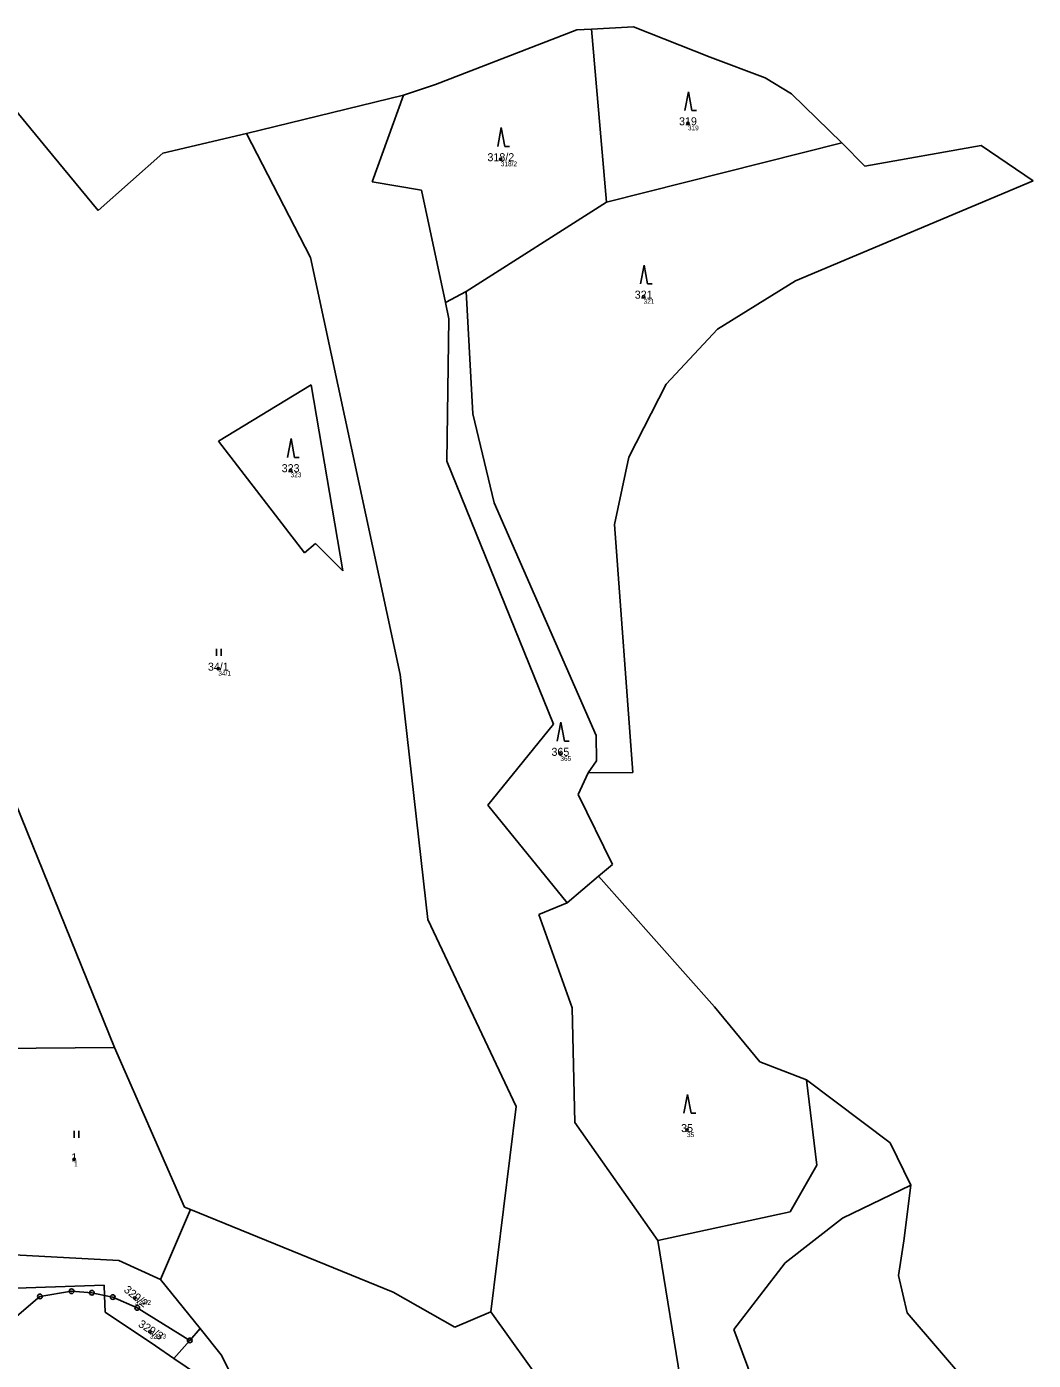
# Model space of a CAD drawing. Extents: x -868010 to -864567, y -1041968 to -1040406.
# Drawn here: x -865068.7 to -864854.9, y -1040959.8 to -1040676.6 of the extents above; entities that cross this region are included whole.
import ezdxf

# ---------------------------------------------------------------- set-up
doc = ezdxf.new("R2010")
doc.units = 0
for name, color, linetype in [('Definiční body', 7, 'Continuous'), ('Hranice parcel', 7, 'Continuous'), ('Parcelní čísla', 7, 'Continuous'), ('Značky bodu BP', 7, 'Continuous'), ('Značky kultur', 7, 'Continuous')]:
    doc.layers.add(name, color=color, linetype=linetype)

msp = doc.modelspace()

# ---------------------------------------------------------------- linework, layer by layer
at = {"layer": 'Definiční body'}
for centre in [(-864928.24, -1040697.07994), (-864967.98, -1040704.70994), (-864937.65, -1040733.90994), (-865012.62, -1040770.75994), (-865027.97, -1040812.91994), (-864955.33, -1040831.00994), (-864928.43, -1040910.92994), (-865058.58, -1040917.14994), (-865045.7, -1040946.55994), (-865042.51, -1040953.70994)]:
    msp.add_circle(centre, 0.25, dxfattribs=at)
at = {"layer": 'Hranice parcel'}
for p, q in [((-864945.5, -1040713.85), (-864948.71, -1040677.1)), ((-865077.15, -1040686.93), (-865063.19, -1040703.84)), ((-864988.64, -1040691.1), (-865021.96, -1040699.26)), ((-864988.64, -1040691.1), (-864995.32, -1040709.49)), ((-864988.64, -1040691.1), (-864981.88, -1040688.87)), ((-865021.96, -1040699.26), (-865039.73, -1040703.45)), ((-865021.96, -1040699.26), (-865008.4, -1040725.6)), ((-864945.5, -1040713.85), (-864895.58, -1040701.25)), ((-864895.58, -1040701.25), (-864890.64, -1040706.19)), ((-864890.64, -1040706.19), (-864865.98, -1040701.8)), ((-864865.98, -1040701.8), (-864854.89, -1040709.33)), ((-865063.19, -1040703.84), (-865053.49, -1040715.59)), ((-865039.73, -1040703.45), (-865053.49, -1040715.59)), ((-864995.32, -1040709.49), (-864984.8, -1040711.27)), ((-864984.8, -1040711.27), (-864979.73, -1040735.14)), ((-864905.4, -1040730.54), (-864854.89, -1040709.33)), ((-864975.3, -1040732.8), (-864945.5, -1040713.85)), ((-865008.4, -1040725.6), (-864989.33, -1040814.16)), ((-864979.73, -1040735.14), (-864975.3, -1040732.8)), ((-864975.3, -1040732.8), (-864973.89, -1040758.79)), ((-864978.98, -1040738.62), (-864979.73, -1040735.14)), ((-864979.45, -1040768.85), (-864978.98, -1040738.62)), ((-865027.93, -1040764.58), (-865008.26, -1040752.62)), ((-865008.26, -1040752.62), (-865001.5, -1040792.14)), ((-864973.89, -1040758.79), (-864969.37, -1040777.68)), ((-865009.66, -1040788.34), (-865027.93, -1040764.58)), ((-864979.45, -1040768.85), (-864956.82, -1040824.71)), ((-864969.37, -1040777.68), (-864947.74, -1040827.13)), ((-865007.36, -1040786.32), (-865009.66, -1040788.34)), ((-865001.5, -1040792.14), (-865007.36, -1040786.32)), ((-864989.33, -1040814.16), (-864983.44, -1040866.22)), ((-864970.76, -1040841.94), (-864956.82, -1040824.71)), ((-864947.74, -1040827.13), (-864947.63, -1040832.5)), ((-864947.63, -1040832.5), (-864949.44, -1040835.03)), ((-864951.53, -1040839.63), (-864949.44, -1040835.03)), ((-865050, -1040893.36), (-865070.98, -1040841.62)), ((-864944.28, -1040854.49), (-864951.53, -1040839.63)), ((-864953.86, -1040862.63), (-864970.76, -1040841.94)), ((-864947.26, -1040856.97), (-864944.28, -1040854.49)), ((-864953.86, -1040862.63), (-864947.26, -1040856.97)), ((-864922.63, -1040884.77), (-864947.26, -1040856.97)), ((-864959.93, -1040865.15), (-864953.86, -1040862.63)), ((-864983.44, -1040866.22), (-864964.68, -1040905.94)), ((-864952.82, -1040884.99), (-864959.93, -1040865.15)), ((-864952.23, -1040909.28), (-864952.82, -1040884.99)), ((-864912.96, -1040896.41), (-864922.63, -1040884.77)), ((-865050, -1040893.36), (-865089.72, -1040893.69)), ((-865035.13, -1040927.32), (-865050, -1040893.36)), ((-864903.03, -1040900.28), (-864912.96, -1040896.41)), ((-864903.03, -1040900.28), (-864900.89, -1040918.36)), ((-864885.3, -1040913.62), (-864903.03, -1040900.28)), ((-864964.68, -1040905.94), (-864970.13, -1040949.51)), ((-864934.65, -1040934.35), (-864952.23, -1040909.28)), ((-864880.89, -1040922.66), (-864885.3, -1040913.62)), ((-864906.52, -1040928.28), (-864900.89, -1040918.36)), ((-864880.89, -1040922.66), (-864895.42, -1040929.61)), ((-864882.38, -1040934.48), (-864880.89, -1040922.66)), ((-865033.9, -1040927.77), (-865040.24, -1040942.68)), ((-865033.9, -1040927.77), (-865035.13, -1040927.32)), ((-864990.86, -1040945.37), (-865033.9, -1040927.77)), ((-864934.65, -1040934.35), (-864906.52, -1040928.28)), ((-864895.42, -1040929.61), (-864907.56, -1040939.09)), ((-864928.73, -1040970.79), (-864934.65, -1040934.35)), ((-864883.55, -1040941.82), (-864882.38, -1040934.48)), ((-865073.93, -1040937.25), (-865049.11, -1040938.65)), ((-865049.11, -1040938.65), (-865040.24, -1040942.68)), ((-864907.56, -1040939.09), (-864918.51, -1040953.31)), ((-865031.84, -1040953.09), (-865040.24, -1040942.68)), ((-864881.68, -1040949.76), (-864883.55, -1040941.82)), ((-865052.21, -1040943.87), (-865080.29, -1040944.86)), ((-865052.14, -1040946.04), (-865052.21, -1040943.87)), ((-865052.03, -1040949.57), (-865052.14, -1040946.04)), ((-864977.77, -1040952.79), (-864990.86, -1040945.37)), ((-865041.34, -1040956.77), (-865052.03, -1040949.57)), ((-864970.13, -1040949.51), (-864977.77, -1040952.79)), ((-864970.13, -1040949.51), (-864948.86, -1040979.05)), ((-864866.15, -1040967.76), (-864881.68, -1040949.76)), ((-865031.84, -1040953.09), (-865034.04, -1040955.61)), ((-865027.34, -1040958.67), (-865031.84, -1040953.09)), ((-864918.51, -1040953.31), (-864913.04, -1040967.97)), ((-865037.38, -1040959.44), (-865041.34, -1040956.77)), ((-865034.04, -1040955.61), (-865037.38, -1040959.44)), ((-865029.54, -1040964.73), (-865037.38, -1040959.44)), ((-865027.34, -1040958.67), (-865013.57, -1040985.88))]:
    msp.add_line(p, q, dxfattribs=at)
for points in [[(-864948.71, -1040677.1), (-864951.85, -1040677.21), (-864981.88, -1040688.87)], [(-864948.71, -1040677.1), (-864939.77, -1040676.56), (-864923.5, -1040683.04), (-864911.85, -1040687.41), (-864906.26, -1040690.81), (-864895.58, -1040701.25)], [(-864905.4, -1040730.54), (-864921.99, -1040740.82), (-864932.87, -1040752.51), (-864940.81, -1040767.99), (-864943.81, -1040782.28)], [(-864943.81, -1040782.28), (-864939.96, -1040834.96), (-864949.44, -1040835.03)], [(-865087.04, -1040964.3), (-865065.86, -1040946.27), (-865059.13, -1040945.17), (-865054.8, -1040945.48), (-865052.14, -1040946.04)], [(-865052.14, -1040946.04), (-865050.38, -1040946.41), (-865045.18, -1040948.68), (-865034.04, -1040955.61)]]:
    msp.add_lwpolyline(points, dxfattribs=at)
at = {"layer": 'Značky bodu BP'}
for centre, radius in [((-865065.86, -1040946.26988), 0.5), ((-865065.86, -1040946.26988), 0.0303), ((-865059.13, -1040945.16988), 0.5), ((-865059.13, -1040945.16988), 0.0303), ((-865054.8, -1040945.47988), 0.5), ((-865054.8, -1040945.47988), 0.0303), ((-865050.38, -1040946.40988), 0.5), ((-865050.38, -1040946.40988), 0.0303), ((-865045.18, -1040948.67988), 0.5), ((-865045.18, -1040948.67988), 0.0303), ((-865034.04, -1040955.60988), 0.5), ((-865034.04, -1040955.60988), 0.0303)]:
    msp.add_circle(centre, radius, dxfattribs=at)
at = {"layer": 'Značky kultur'}
for p, q in [((-864928.14, -1040690.38), (-864928.89, -1040694.38)), ((-864927.39, -1040694.38), (-864928.14, -1040690.38)), ((-864927.39, -1040694.38), (-864926.394, -1040694.38)), ((-864967.88, -1040698.01), (-864968.63, -1040702.01)), ((-864967.13, -1040702.01), (-864967.88, -1040698.01)), ((-864967.13, -1040702.01), (-864966.134, -1040702.01)), ((-864937.55, -1040727.21), (-864938.3, -1040731.21)), ((-864936.8, -1040731.21), (-864937.55, -1040727.21)), ((-864936.8, -1040731.21), (-864935.804, -1040731.21)), ((-865012.52, -1040764.06), (-865013.27, -1040768.06)), ((-865011.77, -1040768.06), (-865012.52, -1040764.06)), ((-865011.77, -1040768.06), (-865010.774, -1040768.06)), ((-865028.381, -1040810.22), (-865028.381, -1040808.72)), ((-865027.38, -1040810.22), (-865027.38, -1040808.72)), ((-864955.23, -1040824.31), (-864955.98, -1040828.31)), ((-864954.48, -1040828.31), (-864955.23, -1040824.31)), ((-864954.48, -1040828.31), (-864953.484, -1040828.31)), ((-864928.33, -1040903.35), (-864929.08, -1040907.35)), ((-864927.58, -1040907.35), (-864928.33, -1040903.35)), ((-864927.58, -1040907.35), (-864926.584, -1040907.35)), ((-865058.591, -1040912.58), (-865058.591, -1040911.08)), ((-865057.59, -1040912.58), (-865057.59, -1040911.08))]:
    msp.add_line(p, q, dxfattribs=at)

# ---------------------------------------------------------------- texts
at = {"layer": 'Definiční body'}
for s, height, p in [('319', 0.999996, (-864928.24, -1040698.569)), ('318/2', 0.999996, (-864967.98, -1040706.199)), ('321', 0.999996, (-864937.65, -1040735.399)), ('323', 0.999996, (-865012.62, -1040772.249)), ('34/1', 0.999996, (-865027.97, -1040814.409)), ('365', 0.999996, (-864955.33, -1040832.499)), ('35', 0.999996, (-864928.43, -1040912.419)), ('1', 1, (-865058.58, -1040918.639)), ('329/2', 0.999996, (-865045.7, -1040948.049)), ('329/3', 0.999996, (-865042.51, -1040955.199))]:
    msp.add_text(s, height=height, dxfattribs=at).set_placement(p)
at = {"layer": 'Parcelní čísla'}
for s, height, p in [('319', 1.699998, (-864930.13, -1040697.505)), ('318/2', 1.699998, (-864970.816, -1040705.135)), ('321', 1.699998, (-864939.54, -1040734.335)), ('323', 1.699998, (-865014.51, -1040771.185)), ('34/1', 1.699998, (-865030.175, -1040813.345)), ('365', 1.699998, (-864957.22, -1040831.435)), ('35', 1.699998, (-864929.69, -1040911.355)), ('1', 1.7, (-865059.21, -1040917.575))]:
    msp.add_text(s, height=height, dxfattribs=at).set_placement(p)
for s, rotation, p in [('329/2', 321, (-865048.171, -1040945.105)), ('329/3', 327, (-865045.12, -1040952.521))]:
    msp.add_text(s, height=1.699998, rotation=rotation, dxfattribs=at).set_placement(p)

doc.saveas('drawing.dxf')
